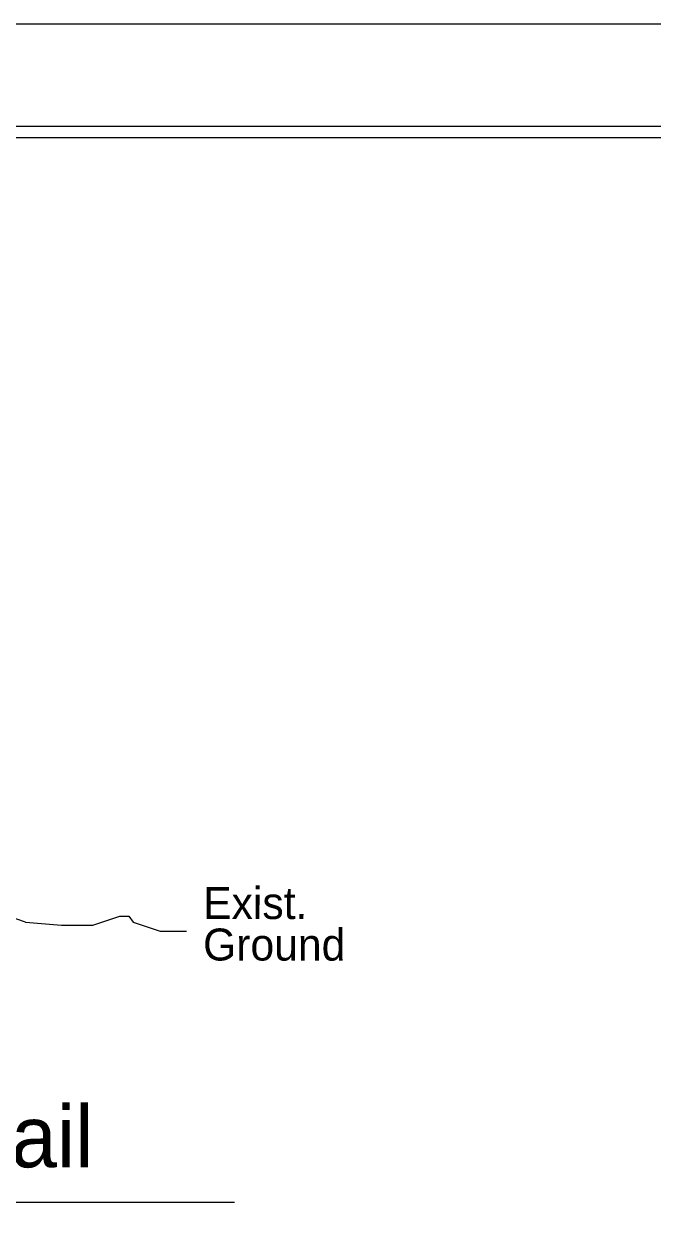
# Model space of a CAD drawing. Extents: x 1497225 to 1499181, y 579958 to 582278.
# Drawn here: x 1498550.6 to 1498688.6, y 582014.3 to 582278 of the extents above; entities that cross this region are included whole.
import ezdxf

# ---------------------------------------------------------------- set-up
doc = ezdxf.new("R2010")
doc.units = 0
for name, color, linetype in [('Old_Level_1', 7, 'Continuous'), ('Sheet Cutting Line CELL', 7, 'Continuous'), ('Sheet Plot Border Inside CELL', 7, 'Continuous'), ('Sheet Plot Border Outside CELL', 7, 'Continuous'), ('Sheet Typical CELL', 7, 'Continuous'), ('Typical Text General CELL', 7, 'Continuous')]:
    doc.layers.add(name, color=color, linetype=linetype)

msp = doc.modelspace()

# ---------------------------------------------------------------- linework, layer by layer
at = {"layer": 'Old_Level_1'}
for p, q in [((1498550.92, 582080.99), (1498506.46, 582095.81)), ((1498320.75, 582019.56), (1498596.74, 582019.56))]:
    msp.add_line(p, q, dxfattribs=at)
msp.add_lwpolyline([(1498550.92, 582080.99), (1498558.79, 582080.33), (1498560.76, 582080.33), (1498563.71, 582080.33), (1498565.68, 582080.33), (1498567.65, 582080.99), (1498569.61, 582081.65), (1498571.58, 582082.3), (1498573.55, 582082.3), (1498574.53, 582080.99), (1498576.5, 582080.33), (1498578.47, 582079.68), (1498580.43, 582079.02), (1498586.22, 582079.02)], dxfattribs=at)
at = {"layer": 'Sheet Cutting Line CELL'}
msp.add_line((1498909.23, 582277.96), (1497225.23, 582277.96), dxfattribs=at)
at = {"layer": 'Sheet Plot Border Inside CELL'}
msp.add_lwpolyline([(1498904.73, 582255.51), (1497238.23, 582255.51), (1497238.23, 581200.41), (1498904.73, 581200.41)], close=True, dxfattribs=at)
at = {"layer": 'Sheet Plot Border Outside CELL'}
msp.add_lwpolyline([(1498909.23, 582277.96), (1497225.23, 582277.96), (1497225.23, 581177.96), (1498909.23, 581177.96)], close=True, dxfattribs=at)
at = {"layer": 'Sheet Typical CELL'}
msp.add_lwpolyline([(1498892.23, 582252.96), (1497392.23, 582252.96), (1497392.23, 581202.96), (1498892.23, 581202.96)], close=True, dxfattribs=at)

# ---------------------------------------------------------------- texts
at = {"layer": 'Old_Level_1'}
for s, p in [('Exist.', (1498589.87, 582081.66)), ('Ground', (1498589.86, 582072.56))]:
    msp.add_text(s, height=7, rotation=359.9492, dxfattribs=at).set_placement(p)
at = {"layer": 'Typical Text General CELL'}
msp.add_text('Shoulder Widening Detail', height=13.52, dxfattribs=at).set_placement((1498361.8, 582027.19))

doc.saveas('drawing.dxf')
